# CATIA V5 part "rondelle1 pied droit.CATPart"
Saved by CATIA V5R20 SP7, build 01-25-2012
Part number: rondelle 1 pied droit
Bounding box of the stored display mesh (mm): x 19.398 to 32.022, y -79 to -65, z -2.293 to 5.573
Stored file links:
  F:\Travaux\Modélisations\CFAO_2011\CFAO_2011_MMS\CFAO_2011_MMS_DONE\CFAO_2011_MMS_jboiteux\Catia\rondelle1 pied droit.CATPart
  U:\finthinkmotion\stepper.CATProduct
  F:\Travaux\Modélisations\CFAO_2011\CFAO_2011_MMS\CFAO_2011_MMS_DONE\CFAO_2011_MMS_jboiteux\Catia\entretoise pied droit.CATPart
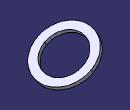
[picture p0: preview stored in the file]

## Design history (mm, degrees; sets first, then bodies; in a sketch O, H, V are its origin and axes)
Set1
  DatumSurface1: linked copy from another document
Body1 (main body)
  Sketch1 on face of DatumSurface1, origin (7.3878, 0, 12.796), H (0, 1, 0), V (-0.866, 0, 0.5)
    projected circle E1 centre (-72, -21.4454) radius 7 from edge of DatumSurface1
    projected circle E2 centre (-72, -21.4454) radius 5 from edge of DatumSurface1
  Pad1: profile Sketch1, direction (-0.5, 0, -0.866), length 1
